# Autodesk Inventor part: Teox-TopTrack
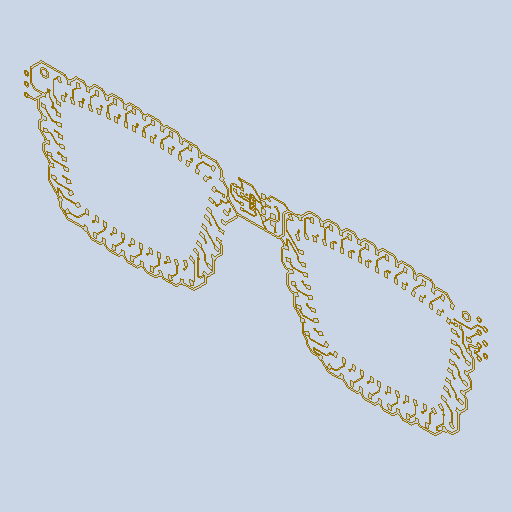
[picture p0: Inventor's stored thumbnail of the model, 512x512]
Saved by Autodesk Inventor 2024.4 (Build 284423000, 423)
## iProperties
Created: 2025-05
Part Number: Teox-TopTrack
Material: Generic
Document SubType Name: Modeling
Designer: AdminForWorker
Density: 1 g/cm^3
Appearance: Default
Title: Teox-TopTrack
Author: AdminForWorker
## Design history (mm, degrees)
feature "Composite1"
body "Srf1"
